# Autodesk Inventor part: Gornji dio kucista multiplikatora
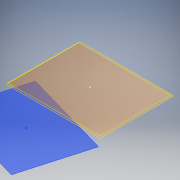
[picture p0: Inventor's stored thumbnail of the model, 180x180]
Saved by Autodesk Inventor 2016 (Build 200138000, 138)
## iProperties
Created: 2015-08
Part Number: Gornji dio kucista multiplikatora
Material: Generic
Document SubType Name: Modeling
Designer: Ugljesa
Density: 1 g/cm^3
Appearance: Default
Author: Ugljesa
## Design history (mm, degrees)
workplane "Work Plane12"
workplane "Work Plane13"
sketch "Sketch22"
  geometry: 1 further point
  constraints: 1 other
body "Solid3"
